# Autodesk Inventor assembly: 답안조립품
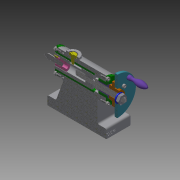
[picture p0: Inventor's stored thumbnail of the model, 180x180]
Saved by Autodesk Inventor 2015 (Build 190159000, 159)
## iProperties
Created: 2022-06
Part Number: 답안조립품
Document SubType Name: Assembly
Designer: 104658
Author: 104658
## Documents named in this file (18)
- C:\Users\104658\Desktop\720606V1008\답안조립품.iam
- C:\Users\104658\Desktop\720606V1008\나사.ipt
- C:\Users\104658\Desktop\720606V1008\나사축.ipt
- C:\Users\104658\Desktop\720606V1008\너트 M8.ipt
- C:\Users\104658\Desktop\720606V1008\돌림판.ipt
- C:\Users\104658\Desktop\720606V1008\멈춤나사 M3.ipt
- C:\Users\104658\Desktop\720606V1008\본체.ipt
- C:\Users\104658\Desktop\720606V1008\볼트 M3.ipt
- C:\Users\104658\Desktop\720606V1008\부시.ipt
- C:\Users\104658\Desktop\720606V1008\센터.ipt
- C:\Users\104658\Desktop\720606V1008\센터홀더.ipt
- C:\Users\104658\Desktop\720606V1008\슬리브.ipt
- C:\Users\104658\Desktop\720606V1008\와셔.ipt
- C:\Users\104658\Desktop\720606V1008\중공축.ipt
- C:\Users\104658\Desktop\720606V1008\커버.ipt
- C:\Users\104658\Desktop\720606V1008\키 4 x 4 x 10.ipt
- C:\Users\104658\Desktop\720606V1008\플랜지.ipt
- C:\Users\104658\Desktop\720606V1008\핸들.ipt
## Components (2 placed, 2 different names)
1. 플랜지:1 — 각도:2
2. 핸들:1
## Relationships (1: Angle 1)
- 각도:2 [Angle]: 플랜지:1
